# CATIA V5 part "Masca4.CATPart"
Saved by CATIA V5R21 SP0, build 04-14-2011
Part number: Masca4
Bounding box of the stored display mesh (mm): x -130 to 30, y -30 to 30, z 95 to 155
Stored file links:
  C:\Users\MIRCEA\Desktop\PRRO\CATIAV5\Masca4.CATPart
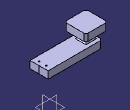
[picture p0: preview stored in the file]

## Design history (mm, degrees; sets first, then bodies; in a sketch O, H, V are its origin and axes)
Body1 (main body)
  Plane1: type Offset, RefPlane xy-plane, Offset 95
  Sketch1 on Plane1, origin (0, 0, 95), H (1, 0, 0), V (0, 1, 0)
    line L1 (30, 0) -> (30, 25)
    line L2 (30, 0) -> (30, -25)
    line L3 (30, -25) -> (-120, -25)
    line L4 (30, 25) -> (-120, 25)
    line L5 (-120, -25) -> (-120, 25)
    length L1 = 25
    length L2 = 25
    length L3 = 150
    vertical: L1 V, L2 V, L5 V
    horizontal: L3 H, L4 H
  Pad1: profile Sketch1, direction (0, 0, 1), length 20
  Plane2: type Offset, RefPlane Plane1, Offset 20
  Sketch2 on Plane2, origin (0, 0, 115), H (1, 0, 0), V (0, 1, 0)
    circle A1 centre (20, 10) radius 2
    circle A2 centre (20, -10) radius 2
    radius A1 = 2
    radius A2 = 2
  Pocket1: profile Sketch2, direction (0, 0, -1), through (limit type 6)
  Sketch3 on Plane2, origin (0, 0, 115), H (1, 0, 0), V (0, 1, 0)
    line L1 (-90, 10) -> (-90, -10)
    line L2 (-90, -10) -> (-110, -10)
    line L3 (-110, -10) -> (-110, 10)
    line L4 (-110, 10) -> (-90, 10)
    distance L2 L4 = 20
    distance L1 L3 = 20
    vertical: L1 V, L3 V
    horizontal: L2 H, L4 H
  Pad2: profile Sketch3, direction (0, 0, 1), length 20
  Plane3: type Offset, RefPlane Plane2, Offset 20
  Sketch4 on Plane3, origin (0, 0, 135), H (1, 0, 0), V (0, 1, 0)
    line L1 (-70, 30) -> (-70, -30)
    line L2 (-70, -30) -> (-130, -30)
    line L3 (-130, -30) -> (-130, 30)
    line L4 (-130, 30) -> (-70, 30)
    distance L2 L4 = 60
    distance L1 L3 = 60
    vertical: L1 V, L3 V
    horizontal: L2 H, L4 H
  Pad3: profile Sketch4, direction (0, 0, 1), length 20
  Chamfer1: length 5, angle 45, on edge [face of Pad3 from Sketch4.L4 | face of Pad3 from Sketch4.L1]; edge [face of Pad3 from Sketch4.L1 | face of Pad3 from Sketch4.L2]; edge [face of Pad3 from Sketch4.L2 | face of Pad3 from Sketch4.L3]; edge [face of Pad3 from Sketch4.L3 | face of Pad3 from Sketch4.L4]
  Chamfer2: length 5, angle 45, on edge [end face of Pad1 | face of Pad2 from Sketch3.L2]; edge [end face of Pad1 | face of Pad2 from Sketch3.L1]; edge [end face of Pad1 | face of Pad2 from Sketch3.L4]; edge [end face of Pad1 | face of Pad2 from Sketch3.L3]; edge [face of Pad2 from Sketch3.L2 | start face of Pad3]; edge [face of Pad2 from Sketch3.L3 | start face of Pad3]; edge [face of Pad2 from Sketch3.L1 | start face of Pad3]; edge [face of Pad2 from Sketch3.L4 | start face of Pad3]; edge [face of Pad1 from Sketch1.L5 | face of Pad1 from Sketch1.L4]; edge [face of Pad1 from Sketch1.L3 | face of Pad1 from Sketch1.L5]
